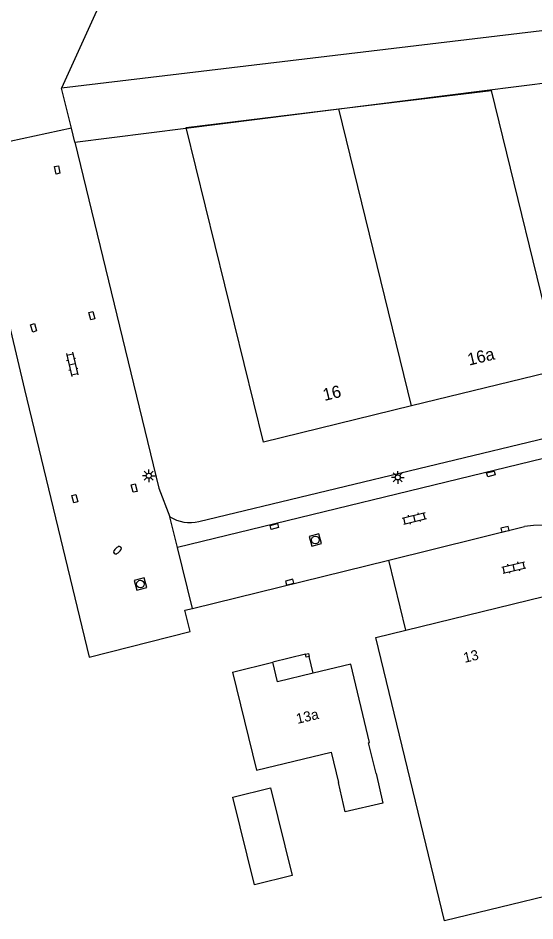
# Model space of a CAD drawing. Extents: x 136000 to 141000, y 400494 to 402006.
# Drawn here: x 138013.6 to 138064.5, y 400601.3 to 400690.1 of the extents above; entities that cross this region are included whole.
import ezdxf

# ---------------------------------------------------------------- set-up
doc = ezdxf.new("R2010")
doc.units = 0
for name, color, linetype in [('gg-afsc-erfafscheiding', 7, 'Continuous'), ('gg-afsc-hekwerk', 7, 'Continuous'), ('gg-anno-huisnummerreeks BGT', 7, 'Continuous'), ('gg-bbg-gedigitaliseerde bebouwing', 7, 'Continuous'), ('gg-bbg-gedigitaliseerde bijgebouw', 7, 'Continuous'), ('gg-bbg-hoofdgebouw', 7, 'Continuous'), ('gg-bbg-onder overbouw', 7, 'Continuous'), ('gg-bbg-pand overbouw', 7, 'Continuous'), ('gg-bbg-pilaar onder overbouw', 7, 'Continuous'), ('gg-bbg-pilaar pand', 7, 'Continuous'), ('gg-knt-verharding', 7, 'Continuous'), ('gt-anno-plantopografie huisnummer', 7, 'Continuous'), ('gt-bbg-plantopografie pand', 7, 'Continuous'), ('gt-bbg-plantopografie tussenscheiding', 7, 'Continuous'), ('gt-grn-groengrens', 7, 'Continuous'), ('gt-grn-weggrens', 7, 'Continuous'), ('gt-symb-brandkraan', 7, 'Continuous'), ('gt-symb-klinker verharding', 7, 'Continuous'), ('gt-symb-kolk', 7, 'Continuous'), ('gt-symb-kolk center center', 7, 'Continuous'), ('gt-symb-lichtmast', 7, 'Continuous'), ('gt-symb-rioolschacht', 7, 'Continuous')]:
    doc.layers.add(name, color=color, linetype=linetype)

# ---------------------------------------------------------------- blocks, each defined once
blk = doc.blocks.new('gt0-LMAST')
at = {"layer": 'gt-symb-lichtmast'}
for p, q in [((-0.182, 0.173), (-0.447, 0.438)), ((-0.005, 0.246), (-0.005, 0.621)), ((0.172, 0.173), (0.437, 0.438)), ((-0.255, -0.004), (-0.63, -0.004)), ((-0.182, -0.181), (-0.447, -0.446)), ((-0.005, -0.254), (-0.005, -0.629)), ((0.437, -0.446), (0.172, -0.181)), ((0.245, -0.004), (0.62, -0.004))]:
    blk.add_line(p, q, dxfattribs=at)
blk.add_circle((-0.005, -0.004), 0.25, dxfattribs=at)
blk = doc.blocks.new('gt0-KL1')
at = {"layer": 'gt-symb-klinker verharding'}
for p, q in [((-1.15, 0.3), (1.15, 0.3)), ((-1, -0.3), (-1, 0.3)), ((-0.5, 0.3), (-0.5, 0.45)), ((0, -0.3), (0, 0.3)), ((0.5, 0.3), (0.5, 0.45)), ((1, -0.3), (1, 0.3)), ((-1.15, -0.3), (1.15, -0.3)), ((-0.5, -0.45), (-0.5, -0.3)), ((0.5, -0.45), (0.5, -0.3))]:
    blk.add_line(p, q, dxfattribs=at)
blk = doc.blocks.new('gt0-KOLKCC')
at = {"layer": 'gt-symb-kolk center center'}
blk.add_lwpolyline([(-0.375, 0.2), (0.375, 0.2), (0.375, -0.2), (-0.375, -0.2)], close=True, dxfattribs=at)
blk = doc.blocks.new('gt0-KOLK')
at = {"layer": 'gt-symb-kolk'}
blk.add_lwpolyline([(0, 0), (0.375, 0), (0.375, 0.4), (-0.375, 0.4), (-0.375, 0), (0, 0)], dxfattribs=at)
blk = doc.blocks.new('gt0-RS')
at = {"layer": 'gt-symb-rioolschacht'}
blk.add_lwpolyline([(-0.5, -0.5), (0.5, -0.5), (0.5, 0.5), (-0.5, 0.5)], close=True, dxfattribs=at)
blk.add_circle((0, 0), 0.375, dxfattribs=at)
blk = doc.blocks.new('gt0-BR')
at = {"layer": 'gt-symb-brandkraan'}
for centre, radius, start, end in [((-0.244, 0), 0.206, 107.56694, 252.43307), ((0.599, -2.664), 3, 106.89205, 107.56694), ((0, -0.691), 0.938, 73.10799, 106.89205), ((-0.599, -2.664), 3, 72.43309, 73.10799), ((0.244, 0), 0.206, 287.56695, 72.43309), ((0.599, 2.664), 3, 252.43307, 253.10797), ((0, 0.691), 0.938, 253.10797, 286.89206), ((-0.599, 2.664), 3, 286.89206, 287.56695)]:
    blk.add_arc(centre, radius, start, end, dxfattribs=at)

msp = doc.modelspace()

# ---------------------------------------------------------------- linework, layer by layer
at = {"layer": 'gg-afsc-erfafscheiding'}
msp.add_line((138019.194, 400677.944), (138073.302, 400684.739), dxfattribs=at)
at = {"layer": 'gg-afsc-hekwerk'}
for p, q in [((138008.579, 400677.113), (138014.235, 400653.582)), ((138031.384, 400640.616), (138079.36, 400652.183))]:
    msp.add_line(p, q, dxfattribs=at)
msp.add_lwpolyline([(138019.194, 400677.944), (138027.46, 400643.885), (138028.532, 400641.067)], dxfattribs=at)
msp.add_arc((138030.492, 400644.221), 3.713, 238.13472, 283.8932, dxfattribs=at)
at = {"layer": 'gg-bbg-gedigitaliseerde bebouwing'}
for points in [[(138048.821, 400615.805), (138048.094, 400618.832), (138048.193, 400618.856), (138046.34, 400626.57)], [(138034.7, 400625.79), (138037.046, 400616.148), (138044.402, 400617.916), (138045.123, 400614.916)], [(138048.821, 400615.805), (138049.494, 400612.886), (138045.788, 400612.032), (138045.123, 400614.916)]]:
    msp.add_lwpolyline(points, dxfattribs=at)
at = {"layer": 'gg-bbg-gedigitaliseerde bijgebouw'}
msp.add_lwpolyline([(138040.568, 400605.778), (138036.861, 400604.859), (138034.727, 400613.467), (138038.433, 400614.386), (138040.568, 400605.778)], dxfattribs=at)
at = {"layer": 'gg-bbg-hoofdgebouw'}
for p, q in [((138051.76, 400629.913), (138065.31, 400633.21)), ((138034.7, 400625.79), (138038.67, 400626.77)), ((138046.34, 400626.57), (138042.63, 400625.679))]:
    msp.add_line(p, q, dxfattribs=at)
msp.add_lwpolyline([(138065.31, 400633.21), (138072.06, 400605.3), (138055.57, 400601.3), (138048.79, 400629.19), (138051.76, 400629.913)], dxfattribs=at)
at = {"layer": 'gg-bbg-onder overbouw'}
msp.add_lwpolyline([(138042.63, 400625.679), (138039.133, 400624.84), (138038.67, 400626.77)], dxfattribs=at)
at = {"layer": 'gg-bbg-pand overbouw'}
for p, q in [((138041.874, 400627.541), (138038.67, 400626.77)), ((138042.63, 400625.679), (138042.236, 400627.319))]:
    msp.add_line(p, q, dxfattribs=at)
at = {"layer": 'gg-bbg-pilaar onder overbouw'}
msp.add_lwpolyline([(138042.236, 400627.319), (138041.944, 400627.249), (138041.874, 400627.541)], dxfattribs=at)
at = {"layer": 'gg-bbg-pilaar pand'}
msp.add_lwpolyline([(138041.874, 400627.541), (138042.166, 400627.611), (138042.236, 400627.319)], dxfattribs=at)
at = {"layer": 'gg-knt-verharding'}
for p, q in [((138018.852, 400679.307), (138008.579, 400677.113)), ((138019.194, 400677.944), (138018.852, 400679.307)), ((138050.079, 400636.815), (138063.42, 400640.1)), ((138030.752, 400632.055), (138050.079, 400636.815)), ((138051.76, 400629.913), (138050.079, 400636.815))]:
    msp.add_line(p, q, dxfattribs=at)
msp.add_lwpolyline([(138014.235, 400653.582), (138020.584, 400627.259), (138030.518, 400629.769), (138030.017, 400631.874), (138030.752, 400632.055)], dxfattribs=at)
msp.add_arc((138065.486, 400626.507), 13.749, 39.98429, 98.64072, dxfattribs=at)
at = {"layer": 'gt-bbg-plantopografie pand'}
msp.add_line((138030.128, 400679.385), (138045.146, 400681.195), dxfattribs=at)
for points in [[(138045.146, 400681.195), (138060.164, 400683.004), (138066.878, 400655.537), (138052.307, 400651.976)], [(138052.307, 400651.976), (138037.736, 400648.414), (138030.128, 400679.385)]]:
    msp.add_lwpolyline(points, dxfattribs=at)
at = {"layer": 'gt-bbg-plantopografie tussenscheiding'}
msp.add_line((138052.307, 400651.976), (138045.146, 400681.195), dxfattribs=at)
at = {"layer": 'gt-grn-groengrens'}
for p in [(138072.075, 400689.714), (138018.852, 400679.307)]:
    msp.add_line(p, (138017.867, 400683.239), dxfattribs=at)
msp.add_lwpolyline([(138024.769, 400732.169), (138022.956, 400694.476), (138017.867, 400683.239)], dxfattribs=at)
at = {"layer": 'gt-grn-weggrens'}
for p, q in [((138079.802, 400650.325), (138029.276, 400638.048)), ((138029.276, 400638.048), (138028.532, 400641.067)), ((138030.752, 400632.055), (138029.276, 400638.048))]:
    msp.add_line(p, q, dxfattribs=at)

# ---------------------------------------------------------------- block references
at = {"layer": 'gt-symb-brandkraan', "rotation": -136.62038199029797}
msp.add_blockref('gt0-BR', (138023.381, 400637.783), dxfattribs=at)
at = {"layer": 'gt-symb-klinker verharding'}
for p, rotation in [((138018.925, 400656.076), -76.46414363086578), ((138052.597, 400640.907), 14.008443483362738), ((138062.382, 400636.074), 12.88297947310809)]:
    msp.add_blockref('gt0-KL1', p, dxfattribs=dict(at, rotation=rotation))
at = {"layer": 'gt-symb-kolk'}
for p, rotation in [((138061.553, 400639.643), 13.827795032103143), ((138040.379, 400634.449), 13.827795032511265)]:
    msp.add_blockref('gt0-KOLK', p, dxfattribs=dict(at, rotation=rotation))
at = {"layer": 'gt-symb-kolk center center'}
for p, rotation in [((138017.457, 400675.201), -79.10581701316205), ((138020.849, 400660.855), -75.28268885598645), ((138015.127, 400659.662), -73.73979529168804), ((138060.12, 400645.282), -165.35262472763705), ((138025.02, 400643.888), 103.73679090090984), ((138019.187, 400642.856), 105.18978716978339), ((138038.806, 400640.111), -164.6292745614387)]:
    msp.add_blockref('gt0-KOLKCC', p, dxfattribs=dict(at, rotation=rotation))
at = {"layer": 'gt-symb-lichtmast'}
for p in [(138026.467, 400645.113), (138050.964, 400644.943)]:
    msp.add_blockref('gt0-LMAST', p, dxfattribs=at)
at = {"layer": 'gt-symb-rioolschacht'}
for p, rotation in [((138042.846, 400638.785), 105.18978717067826), ((138025.642, 400634.449), -74.93576605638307)]:
    msp.add_blockref('gt0-RS', p, dxfattribs=dict(at, rotation=rotation))

# ---------------------------------------------------------------- texts
at = {"layer": 'gg-anno-huisnummerreeks BGT'}
for s, rotation, p in [('13', 13.6, (138057.553, 400626.692)), ('13a', 13.5, (138041.091, 400620.682))]:
    msp.add_text(s, height=1, rotation=rotation, dxfattribs=at).set_placement(p)
at = {"layer": 'gt-anno-plantopografie huisnummer'}
for s, p in [('16a', (138057.98, 400655.936)), ('16', (138043.749, 400652.457))]:
    msp.add_text(s, height=1.2, rotation=13.73679, dxfattribs=at).set_placement(p)

doc.saveas('drawing.dxf')
